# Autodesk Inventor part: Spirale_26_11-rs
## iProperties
Created: 2004-11
Part Number: Spirale_26_11-rs
Cost Center: 1,778 kg
Material: S355 J2G3
Document SubType Name: Blech
Designer: ahuetter
Authority: 226194,67 mm^3
Manufacturer: Standard
Standards Organization: Custom
SaveDate: 2004-11-25
SaveTime: 16:03
TotalMass: 1,778 kg
TotalVolume: 226194,67 mm^3
Author: ahuetter
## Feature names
1. Spirale1
